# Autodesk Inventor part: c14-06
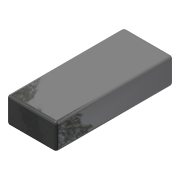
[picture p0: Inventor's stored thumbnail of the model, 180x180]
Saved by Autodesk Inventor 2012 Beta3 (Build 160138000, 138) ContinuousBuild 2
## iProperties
Created: 2011-01
Part Number: c14-06
Material: Default
Document SubType Name: Modeling
Designer: Beta-8540w
Density: 1 g/cm^3
Author: Beta-8540w
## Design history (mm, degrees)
sketch "Sketch1"
  geometry: L1 (-69.571, 93.684)-(-31.571, 93.684); L2 (-31.571, 93.684)-(-31.571, 3.684); L3 (-31.571, 3.684)-(-69.571, 3.684); L4 (-69.571, 3.684)-(-69.571, 93.684); 1 further point
  constraints: 8 end point, 2 parallel, 1 horizontal, 1 perpendicular
  dimensions: "d0" = 38 distance of L2.end L3.end; "d1" = 90 distance of L1.end L2.end
extrude "Extrusion1" new body sketch "Sketch1" distance "d2" = 20; taper "d3" = 0 deg
fillet "Fillet1" dims "d4" = 2
body "Solid1"
